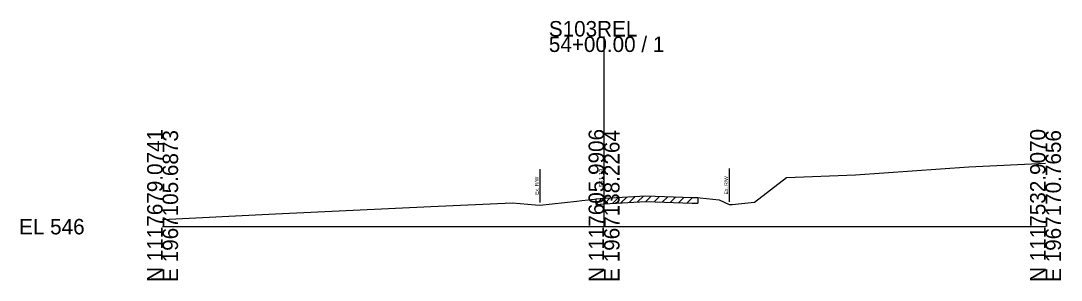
# Model space of a CAD drawing. Extents: x -26 to 163, y -10 to 24518.
# Drawn here: x -25.7 to 162.8, y 4490.3 to 4537.3 of the extents above; entities that cross this region are included whole.
import ezdxf

# ---------------------------------------------------------------- set-up
doc = ezdxf.new("R2010")
doc.units = 0
for name, color, linetype in [('RD_GPK_XS_Cell', 7, 'Continuous'), ('RD_XS_ExGround', 7, 'Continuous'), ('RD_XS_ExPaveRet', 7, 'Continuous'), ('RD_XS_ExRW', 7, 'Continuous'), ('RD_XS_TX_Elev_EX', 7, 'Continuous')]:
    doc.layers.add(name, color=color, linetype=linetype)

msp = doc.modelspace()

# ---------------------------------------------------------------- linework, layer by layer
at = {"layer": 'RD_GPK_XS_Cell'}
for p, q in [((80, 4500), (80, 4534.43)), ((0, 4500), (80, 4500)), ((80, 4500), (160, 4500))]:
    msp.add_line(p, q, dxfattribs=at)
at = {"layer": 'RD_XS_ExGround'}
msp.add_lwpolyline([(0, 4501.29), (20.46, 4502.32), (48.6, 4503.62), (63.42, 4504.3), (67.56, 4503.97), (68.38, 4503.9), (75.04, 4504.64), (75.96, 4504.75), (78.25, 4505), (78.56, 4505.04), (80, 4505.13), (87.6, 4505.55), (95.96, 4505.28), (96.98, 4505.25), (97.42, 4505.2), (100.85, 4504.83), (102.68, 4504), (103.24, 4504.04), (107.29, 4504.45), (113.06, 4508.87), (125.59, 4509.36), (146.12, 4510.82), (160, 4511.48)], dxfattribs=at)
at = {"layer": 'RD_XS_ExPaveRet'}
for p, q in [((78.56, 4504.04), (79.62, 4505.1)), ((78.56, 4504.04), (78.56, 4505.04)), ((78.56, 4504.04), (80, 4504.13)), ((80, 4504.13), (87.6, 4504.55)), ((80.06, 4504.13), (81.12, 4505.19)), ((81.56, 4504.21), (82.62, 4505.27)), ((83.06, 4504.3), (84.12, 4505.36)), ((84.56, 4504.38), (85.62, 4505.44)), ((86.06, 4504.47), (87.12, 4505.53)), ((87.56, 4504.55), (88.53, 4505.52)), ((87.6, 4504.55), (95.96, 4504.28)), ((89.06, 4504.5), (90.03, 4505.47)), ((90.56, 4504.45), (91.53, 4505.42)), ((92.06, 4504.41), (93.03, 4505.37)), ((93.56, 4504.36), (94.53, 4505.32)), ((95.07, 4504.31), (96.03, 4505.28)), ((95.96, 4504.28), (96.98, 4504.25)), ((96.98, 4505.25), (96.98, 4504.25))]:
    msp.add_line(p, q, dxfattribs=at)
at = {"layer": 'RD_XS_ExRW'}
for p, q in [((68.38, 4510.4), (68.38, 4504.4)), ((102.69, 4510.5), (102.69, 4504.5)), ((102.69, 4510.5), (102.69, 4504.5))]:
    msp.add_line(p, q, dxfattribs=at)

# ---------------------------------------------------------------- texts
at = {"layer": 'RD_GPK_XS_Cell'}
for s, p in [('S103REL', (70, 4534.43)), ('54+00.00 / 1', (70, 4531.63)), ('EL 546', (-26, 4498.6))]:
    msp.add_text(s, height=2.8, dxfattribs=at).set_placement(p)
for s, p in [('N 1117679.0741', (0, 4490)), ('E 1967105.6873', (2.8, 4490)), ('N 1117605.9906', (80, 4490)), ('E 1967138.2264', (82.8, 4490)), ('N 1117532.9070', (160, 4490)), ('E 1967170.7656', (162.8, 4490))]:
    msp.add_text(s, height=2.8, rotation=90, dxfattribs=at).set_placement(p)
at = {"layer": 'RD_XS_ExRW'}
for p in [(68.13, 4505.75), (102.44, 4505.84), (102.44, 4505.84)]:
    msp.add_text('Ex. R/W ', height=0.65, rotation=90, dxfattribs=at).set_placement(p)
at = {"layer": 'RD_XS_TX_Elev_EX'}
msp.add_text('551.13', height=0.8, rotation=90, dxfattribs=at).set_placement((79.9, 4507.13))

doc.saveas('drawing.dxf')
